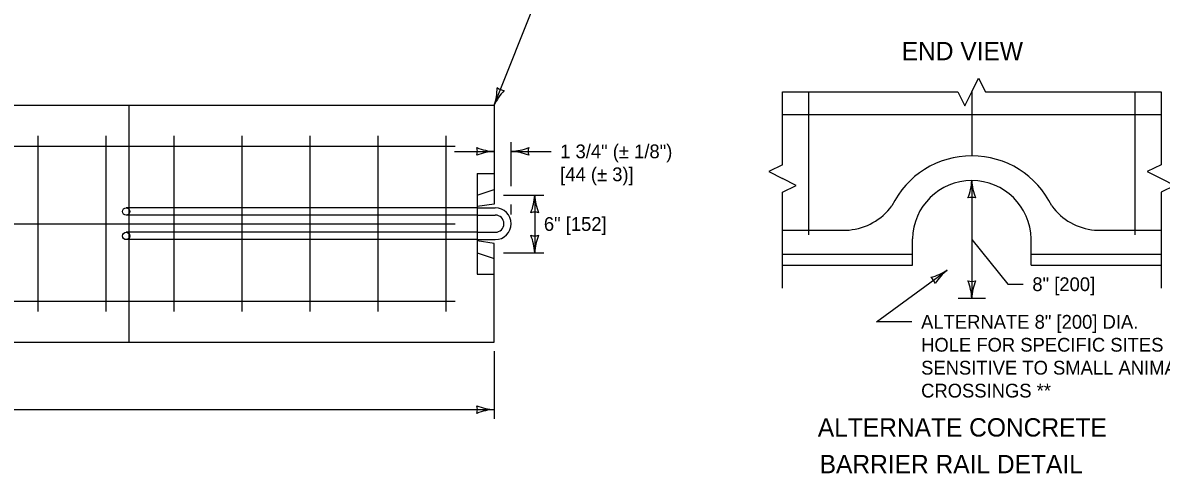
# Model space of a CAD drawing. Extents: x 49991.4 to 50021, y 49987.6 to 50011.4.
# Drawn here: x 50005.623 to 50010.586, y 49993.803 to 49995.768 of the extents above; entities that cross this region are included whole.
import ezdxf

# ---------------------------------------------------------------- set-up
doc = ezdxf.new("R2010")
doc.units = 0
for name, color, linetype in [('Level 1', 7, 'Continuous'), ('Level 2', 7, 'Continuous'), ('Level 3', 7, 'Continuous'), ('Level 4', 7, 'Continuous'), ('Level 6', 7, 'Continuous')]:
    doc.layers.add(name, color=color, linetype=linetype)

msp = doc.modelspace()

# ---------------------------------------------------------------- linework, layer by layer
at = {"layer": 'Level 1'}
for p, q in [((50009.0492, 49995.466), (50009.0492, 49994.8433)), ((50009.7604, 49995.466), (50009.7604, 49995.1873)), ((50010.4716, 49995.466), (50010.4716, 49994.8433)), ((50002.5138, 49995.4076), (50007.6787, 49995.4076)), ((50007.6787, 49995.4076), (50007.6787, 49994.9771)), ((50010.5855, 49995.3656), (50008.9355, 49995.3656)), ((50005.6889, 49995.2739), (50005.6889, 49994.5084)), ((50005.9853, 49995.2739), (50005.9853, 49994.5084)), ((50006.2816, 49995.2739), (50006.2816, 49994.5084)), ((50006.578, 49995.2739), (50006.578, 49994.5084)), ((50006.8743, 49995.2739), (50006.8743, 49994.5084)), ((50007.1707, 49995.2739), (50007.1707, 49994.5084)), ((50007.4671, 49995.2739), (50007.4671, 49994.5084)), ((50002.6839, 49995.2287), (50007.5087, 49995.2287)), ((50007.6036, 49995.0152), (50007.6787, 49995.0402)), ((50007.6036, 49995.0152), (50007.6036, 49994.7647)), ((50007.6787, 49994.9771), (50007.6036, 49994.9656)), ((50007.6036, 49994.9604), (50007.6831, 49994.9604)), ((50007.6036, 49994.9284), (50007.6831, 49994.9284)), ((50002.6839, 49994.8911), (50007.5087, 49994.8911)), ((50007.6036, 49994.8537), (50007.6831, 49994.8537)), ((50008.9355, 49994.8636), (50009.2253, 49994.8636)), ((50009.502, 49994.7107), (50009.502, 49994.8251)), ((50010.019, 49994.7107), (50010.019, 49994.8251)), ((50010.2958, 49994.8636), (50010.5855, 49994.8636)), ((50007.6036, 49994.8217), (50007.6831, 49994.8217)), ((50007.6787, 49994.805), (50007.6036, 49994.8168)), ((50007.6787, 49994.3747), (50007.6787, 49994.805)), ((50007.6036, 49994.7647), (50007.6787, 49994.7397)), ((50008.9355, 49994.7587), (50009.502, 49994.7587)), ((50010.019, 49994.7587), (50010.5855, 49994.7587)), ((50008.9355, 49994.7107), (50009.502, 49994.7107)), ((50010.019, 49994.7107), (50010.5855, 49994.7107)), ((50002.6839, 49994.5537), (50007.5087, 49994.5537)), ((50002.5138, 49994.3747), (50007.6787, 49994.3747))]:
    msp.add_line(p, q, dxfattribs=at)
for centre, radius, start, end in [((50009.7605, 49994.7996), 0.3877, 25.8123, 154.1849), ((50009.7605, 49994.8211), 0.2585, 0.8871, 179.1129), ((50007.6831, 49994.8911), 0.0694, 270, 90), ((50007.6831, 49994.8911), 0.0374, 270, 90), ((50009.2029, 49995.1211), 0.2584, 274.9592, 323.8085), ((50010.3181, 49995.1211), 0.2585, 216.1993, 265.0692)]:
    msp.add_arc(centre, radius, start, end, dxfattribs=at)
at = {"layer": 'Level 3'}
for p, q in [((50007.6787, 49995.4076), (50007.9477, 49996.0849)), ((50007.7526, 49995.0552), (50007.7526, 49995.2466)), ((50007.5053, 49995.2066), (50007.6787, 49995.2066)), ((50007.7526, 49995.2066), (50007.926, 49995.2066)), ((50009.7605, 49995.0796), (50009.7605, 49994.566)), ((50007.7187, 49995.0152), (50007.8949, 49995.0152)), ((50007.7526, 49994.9311), (50007.7526, 49994.9752)), ((50007.8549, 49995.0152), (50007.8549, 49994.7647)), ((50007.7187, 49994.7647), (50007.8949, 49994.7647)), ((50009.3445, 49994.4631), (50009.6531, 49994.6889)), ((50009.7005, 49994.566), (50009.8205, 49994.566)), ((50009.4996, 49994.4631), (50009.3445, 49994.4631)), ((50007.6787, 49994.3347), (50007.6787, 49994.0407)), ((50004.6861, 49994.0807), (50007.6787, 49994.0807))]:
    msp.add_line(p, q, dxfattribs=at)
msp.add_lwpolyline([(50009.7605, 49994.8228), (50009.9184, 49994.6273), (50009.9845, 49994.6273)], dxfattribs=at)
for centre, radius, start, end in [((50007.4582, 49995.4828), 0.233, 341.1658, 0.4156), ((50007.8818, 49995.3171), 0.2223, 135.7945, 155.978), ((50007.726, 49995.5268), 0.0548, 230.4773, 266.1996), ((50007.6879, 49995.4287), 0.2223, 247.456, 267.6395), ((50007.5505, 49995.2066), 0.0548, 342.1388, 17.8612), ((50007.7411, 49995.4393), 0.233, 272.8273, 292.0772), ((50007.8808, 49995.2066), 0.0548, 162.1388, 197.8612), ((50007.6902, 49994.9739), 0.233, 92.8273, 112.0772), ((50007.7434, 49994.9844), 0.2223, 67.456, 87.6395), ((50009.5384, 49995.0888), 0.2223, 337.456, 357.6395), ((50009.9932, 49995.0911), 0.233, 182.8273, 202.0772), ((50007.6327, 49995.0244), 0.2223, 337.456, 357.6395), ((50008.0876, 49995.0267), 0.233, 182.8273, 202.0772), ((50009.7605, 49994.9514), 0.0548, 72.1388, 107.8612), ((50007.8549, 49994.887), 0.0548, 72.1388, 107.8612), ((50007.8549, 49994.8929), 0.0548, 252.1388, 287.8612), ((50007.6222, 49994.7532), 0.233, 2.8273, 22.0772), ((50008.077, 49994.7555), 0.2223, 157.456, 177.6395), ((50009.5293, 49994.8736), 0.2223, 283.6407, 303.8242), ((50009.7998, 49994.5078), 0.233, 129.012, 148.2619), ((50009.5496, 49994.6132), 0.0548, 18.3235, 54.0459), ((50009.7605, 49994.6942), 0.0548, 252.1388, 287.8612), ((50009.5278, 49994.5545), 0.233, 2.8273, 22.0772), ((50009.9826, 49994.5568), 0.2223, 157.456, 177.6395), ((50007.6879, 49994.3028), 0.2223, 247.456, 267.6395), ((50007.5505, 49994.0807), 0.0548, 342.1388, 17.8612), ((50007.6902, 49993.8479), 0.233, 92.8273, 112.0772)]:
    msp.add_arc(centre, radius, start, end, dxfattribs=at)
at = {"layer": 'Level 4'}
for p, q in [((50006.087, 49994.3747), (50006.087, 49995.4076)), ((50007.6036, 49995.1103), (50007.6787, 49995.1103)), ((50007.6036, 49995.1103), (50007.6036, 49995.0152)), ((50007.6036, 49994.9604), (50006.0737, 49994.9604)), ((50007.6036, 49994.9284), (50006.0737, 49994.9284)), ((50007.6036, 49994.8537), (50006.0737, 49994.8537)), ((50007.6036, 49994.8217), (50006.0737, 49994.8217)), ((50007.6036, 49994.7647), (50007.6036, 49994.6718)), ((50007.6036, 49994.6718), (50007.6787, 49994.6718))]:
    msp.add_line(p, q, dxfattribs=at)
for centre in [(50006.0737, 49994.9444), (50006.0737, 49994.8377)]:
    msp.add_circle(centre, 0.016, dxfattribs=at)
at = {"layer": 'Level 6'}
for p, q in [((50009.7604, 49995.466), (50009.7904, 49995.526)), ((50009.7904, 49995.526), (50009.8204, 49995.466)), ((50008.9355, 49995.1484), (50008.9355, 49995.466)), ((50008.9355, 49995.466), (50009.7004, 49995.466)), ((50009.7004, 49995.466), (50009.7304, 49995.406)), ((50009.7304, 49995.406), (50009.7604, 49995.466)), ((50009.8204, 49995.466), (50010.5855, 49995.466)), ((50010.5855, 49995.466), (50010.5855, 49995.1484)), ((50008.9355, 49995.1484), (50008.8755, 49995.1184)), ((50010.5855, 49995.1484), (50010.5255, 49995.1184)), ((50008.8755, 49995.1184), (50008.9355, 49995.0884)), ((50008.9955, 49995.0584), (50008.9355, 49995.0884)), ((50010.5255, 49995.1184), (50010.5855, 49995.0884)), ((50010.5855, 49995.0884), (50010.6455, 49995.0584)), ((50008.9355, 49995.0284), (50008.9955, 49995.0584)), ((50008.9355, 49994.6107), (50008.9355, 49995.0284)), ((50010.6455, 49995.0584), (50010.5855, 49995.0284)), ((50010.5855, 49995.0284), (50010.5855, 49994.6107))]:
    msp.add_line(p, q, dxfattribs=at)

# ---------------------------------------------------------------- texts
at = {"layer": 'Level 2'}
for s, height, p in [('END VIEW', 0.08, (50009.455, 49995.6042)), ('1 3/4" (± 1/8")', 0.06, (50007.966, 49995.1766)), ('[44 (± 3)]', 0.06, (50007.966, 49995.0766)), ('6" [152]', 0.06, (50007.8949, 49994.8599)), ('8" [200]', 0.06, (50010.0245, 49994.5973)), ('ALTERNATE 8" [200] DIA. ', 0.06, (50009.5396, 49994.4331)), ('HOLE FOR SPECIFIC SITES ', 0.06, (50009.5396, 49994.3331)), ('SENSITIVE TO SMALL ANIMAL ', 0.06, (50009.5396, 49994.2331)), ('CROSSINGS **', 0.06, (50009.5396, 49994.1331)), ('ALTERNATE CONCRETE ', 0.08, (50009.0892, 49993.9628)), ('BARRIER RAIL DETAIL', 0.08, (50009.0972, 49993.8028))]:
    msp.add_text(s, height=height, dxfattribs=at).set_placement(p)

doc.saveas('drawing.dxf')
